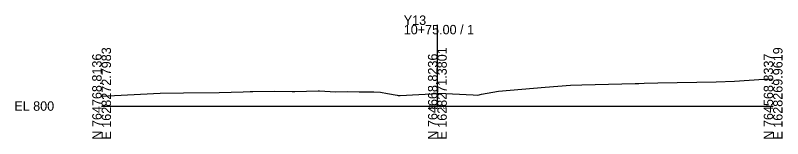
# Model space of a CAD drawing. Extents: x -26 to 203, y -10 to 3517.
# Drawn here: x -25.7 to 202.8, y 1490.3 to 1527 of the extents above; entities that cross this region are included whole.
import ezdxf

# ---------------------------------------------------------------- set-up
doc = ezdxf.new("R2010")
doc.units = 0
for name, color, linetype in [('Default', 7, 'Continuous'), ('Exist Cross Section Cell', 7, 'Continuous'), ('Exist XS Center Line Elevation Label', 7, 'Continuous'), ('Exist XS Ground Line', 7, 'Continuous')]:
    doc.layers.add(name, color=color, linetype=linetype)

msp = doc.modelspace()

# ---------------------------------------------------------------- linework, layer by layer
at = {"layer": 'Exist Cross Section Cell'}
for p, q in [((100, 1500), (100, 1524.14)), ((0, 1500), (100, 1500)), ((100, 1500), (200, 1500))]:
    msp.add_line(p, q, dxfattribs=at)
at = {"layer": 'Exist XS Ground Line'}
msp.add_lwpolyline([(0, 1502.98), (17.43, 1503.81), (24.36, 1503.91), (35.03, 1504.07), (42.13, 1504.26), (44.26, 1504.29), (45.03, 1504.31), (51.58, 1504.39), (56.75, 1504.36), (57.57, 1504.37), (64.51, 1504.54), (64.87, 1504.56), (69.66, 1504.19), (73.17, 1504.36), (76.74, 1504.27), (81.1, 1504.21), (83.04, 1504.17), (85.17, 1503.73), (88, 1503.27), (88.31, 1503.15), (88.92, 1503.17), (100, 1503.76), (100.48, 1503.79), (110.65, 1503.3), (112.08, 1503.25), (113.11, 1503.49), (118.23, 1504.42), (132.15, 1505.63), (139.62, 1506.23), (143.03, 1506.34), (158.91, 1506.71), (160.03, 1506.74), (161.6, 1506.78), (165.69, 1506.89), (183.06, 1507.21), (188.52, 1507.37), (197.24, 1507.97), (200, 1508.05)], dxfattribs=at)

# ---------------------------------------------------------------- texts
at = {"layer": 'Default'}
msp.add_text('-', height=0.0001, dxfattribs=at).set_placement((0, 1500))
at = {"layer": 'Exist Cross Section Cell'}
for s, p in [('Y13', (90, 1524.14)), ('10+75.00 / 1', (90, 1521.34)), ('EL 800', (-26, 1498.6))]:
    msp.add_text(s, height=2.8, dxfattribs=at).set_placement(p)
for s, p in [('N 764768.8136', (0, 1490)), ('E 1628272.7983', (2.8, 1490)), ('N 764668.8236', (100, 1490)), ('E 1628271.3801', (102.8, 1490)), ('N 764568.8337', (200, 1490)), ('E 1628269.9619', (202.8, 1490))]:
    msp.add_text(s, height=2.8, rotation=90, dxfattribs=at).set_placement(p)
at = {"layer": 'Exist XS Center Line Elevation Label'}
msp.add_text('803.76', height=1.2, dxfattribs=at).set_placement((97.43, 1499.16))

doc.saveas('drawing.dxf')
